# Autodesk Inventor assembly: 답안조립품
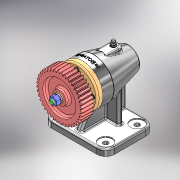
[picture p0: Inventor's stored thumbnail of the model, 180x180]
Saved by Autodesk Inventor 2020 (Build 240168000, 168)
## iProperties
Created: 2024-12
Part Number: 답안조립품
Document SubType Name: Assembly
Designer: 1강의실14
Author: 1강의실14
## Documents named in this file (15)
- C:\Users\1강의실14\Desktop\741204V1013\답안조립품.iam
- C:\Users\1강의실14\Desktop\741204V1013\본체.ipt
- C:\Users\1강의실14\Desktop\741204V1013\앵귤러 볼 베어링 7003A.ipt
- C:\Users\1강의실14\Desktop\741204V1013\축.ipt
- C:\Users\1강의실14\Desktop\741204V1013\앵귤러 볼 제어링 7204A.ipt
- C:\Users\1강의실14\Desktop\741204V1013\오일 실 20 32 8.ipt
- C:\Users\1강의실14\Desktop\741204V1013\육각 소켓 머리 볼트 M4x10.ipt
- C:\Users\1강의실14\Desktop\741204V1013\커버.ipt
- C:\Users\1강의실14\Desktop\741204V1013\스퍼기어.ipt
- C:\Users\1강의실14\Desktop\741204V1013\평행 키 4x4x14.ipt
- C:\Users\1강의실14\Desktop\741204V1013\스프링 와셔 M8.ipt
- C:\Users\1강의실14\Desktop\741204V1013\육각 너트 M8.ipt
- C:\Users\1강의실14\Desktop\741204V1013\평와셔 M8.ipt
- C:\Users\1강의실14\Desktop\741204V1013\그리스 니플 M6x0.75.ipt
- C:\Users\1강의실14\Desktop\741204V1013\실링.ipt
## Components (1 placed, 1 different names)
1. 그리스 니플 M6x0.75:1
